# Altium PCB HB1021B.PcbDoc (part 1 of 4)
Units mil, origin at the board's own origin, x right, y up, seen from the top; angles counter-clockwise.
Board outline 4729.44 x 3075.9 mil, 2 copper layers (Top Layer, Bottom Layer); 113 components, 113 nets, 422 pads, 478 vias.
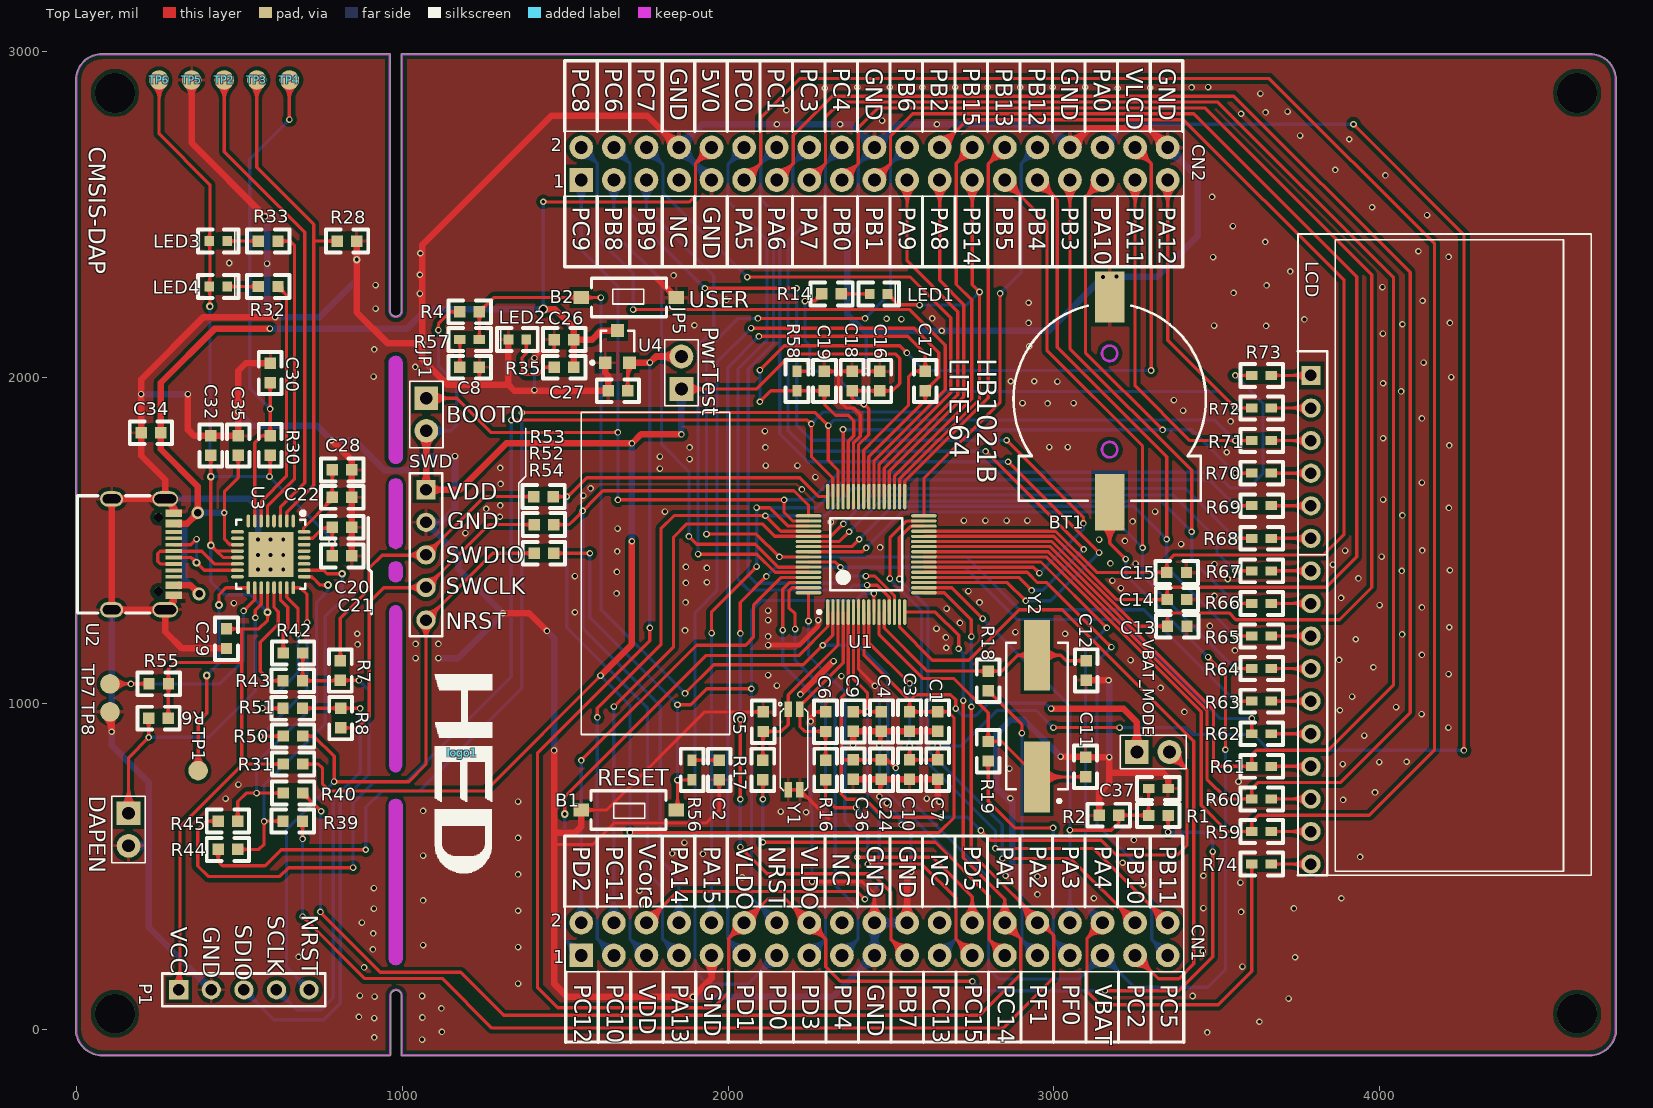
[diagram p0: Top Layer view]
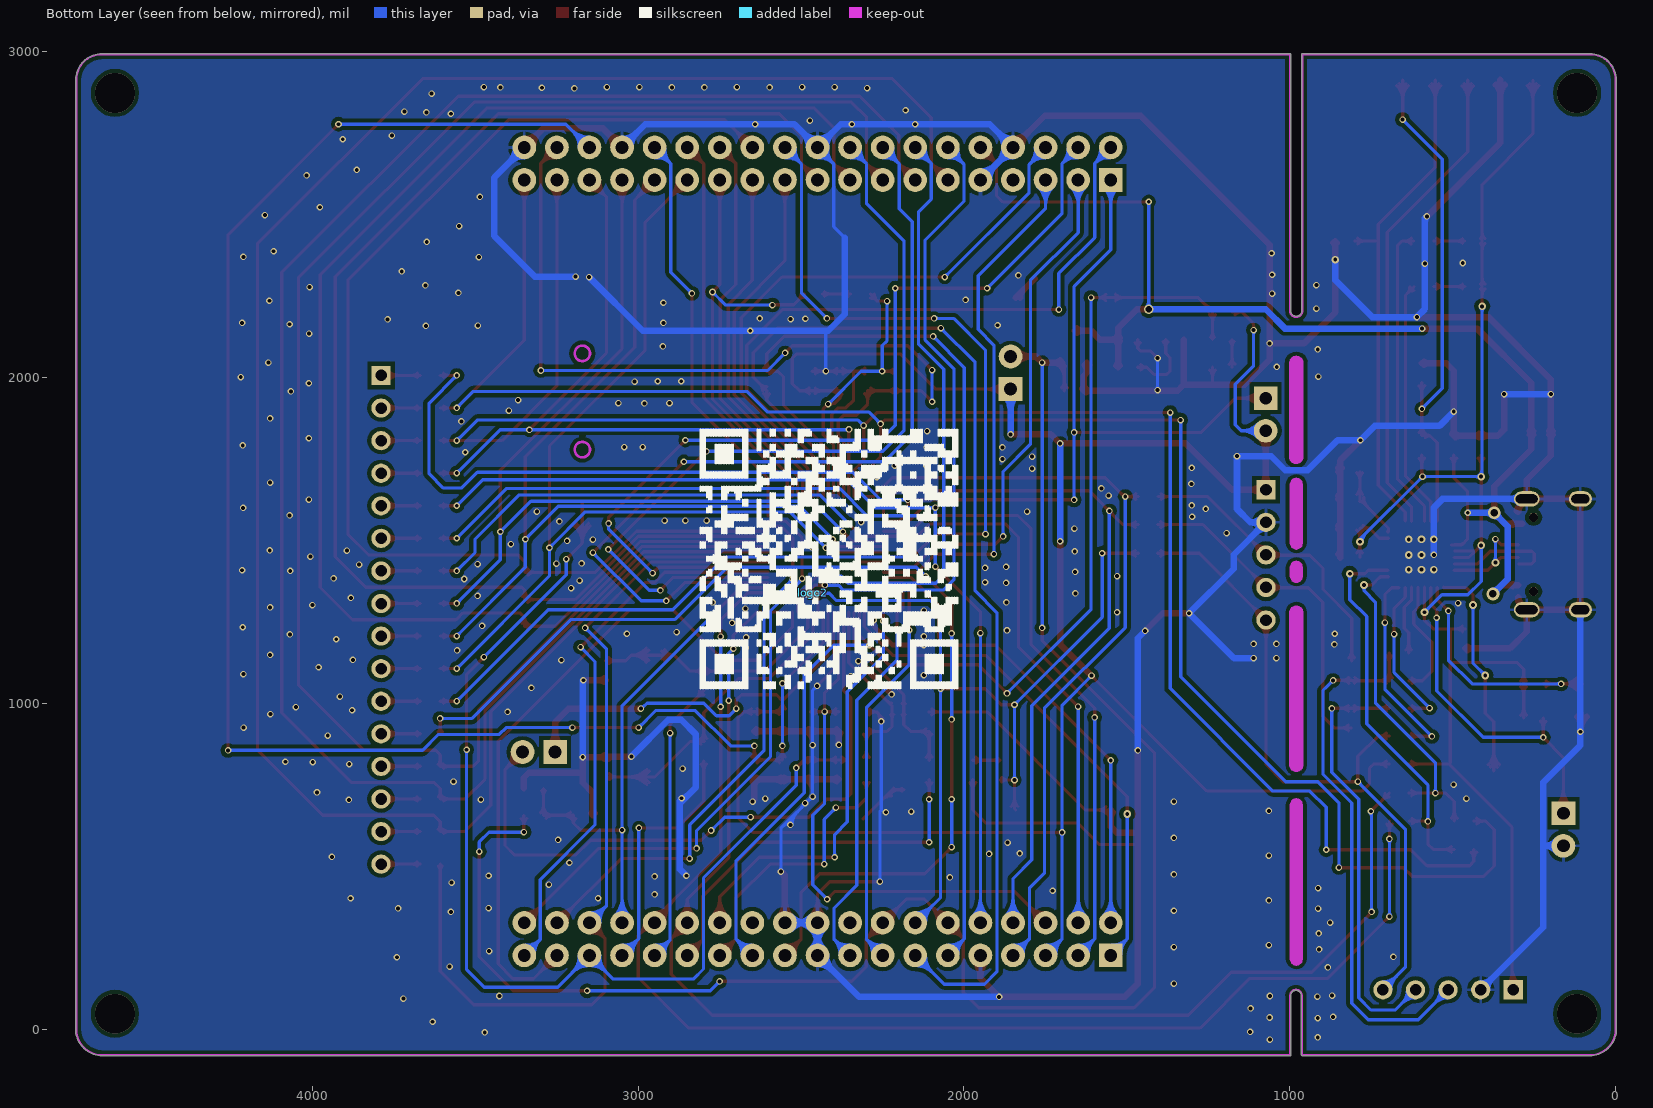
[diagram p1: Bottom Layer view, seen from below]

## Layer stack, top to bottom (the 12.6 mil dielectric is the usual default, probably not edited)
Top Layer: signal copper 1.4
Dielectric: dielectric 12.6, FR-4, Dk 4.8
Bottom Layer: signal copper 1.4

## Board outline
-2.52,0.05 ccw(c78.74,0.05) 78.74,-81.21 ccw(c78.74,-78.69) 78.81,-81.21 962,-81.21 ccw(c962,-78.69) 964.52,-78.69 964.52,103 cw(c981,103) 997.44,104.27 ccw(c999.61,103) 997.09,103 997.09,-78.69 ccw(c999.61,-78.69) 999.61,-81.21 4645.67,-81.21 ccw(c4645.67,0.05) 4726.92,0.05 ccw(c4724.41,0.05) 4726.92,0.07 4726.92,2913.43 cw(c4724.41,2913.43) 4726.92,2913.41 4726.92,2913.43 ccw(c4645.67,2913.43) 4645.73,2994.69 ccw(c4645.67,2992.17) 4645.67,2994.69 1000,2994.69 ccw(c1000,2992.17) 997.48,2992.17 997.48,2204.83 cw(c1000,2204.83) 997.48,2204.88 997.48,2204.83 cw(c980.31,2204.83) 995.99,2197.82 cw(c980.45,2206.4) 963.65,2200.68 cw(c980.31,2204.83) 963.14,2204.77 cw(c980.31,2204.83) 963.14,2204.83 963.14,2992.17 ccw(c960.63,2992.17) 960.12,2994.64 ccw(c959.61,2992.17) 959.61,2994.69 78.8,2994.69 ccw(c78.8,2992.17) 78.74,2994.69 cw(c78.8,2913.43) 78.8,2994.69 78.74,2994.69 ccw(c78.8,2913.43) -2.45,2913.99 ccw(c0,2913.43) -2.51,2913.43
cut-out: 959.99,217 959.99,687 cw(c980,687) 1000.02,687 1000.02,217 cw(c980,217)
cut-out: 959.99,1392 959.99,1416 cw(c980,1416) 1000.02,1416 1000.02,1392 cw(c980,1392)
cut-out: 959.99,1494 959.99,1671 cw(c980,1671) 1000.02,1671 1000.02,1494 cw(c980,1494)
cut-out: 959.99,810 ccw(c980,810) 1000.02,810 1000.02,1280 ccw(c980,1280) 959.99,1280
cut-out: 998.94,1756.79 998.94,2045.37 ccw(c979.25,2045.37) 959.57,2045.37 959.57,1756.79 ccw(c979.25,1756.79)

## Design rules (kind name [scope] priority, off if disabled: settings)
Clearance [(IsPad and InComponent('U1'))] p1: gap=5
Clearance Clearance_CN [(IsPad and InComponent('CN1','CN4','U2'))] p2: gap=6
Clearance Clearance_Pad [All] p3: gap=5
Clearance Clearance_poly [(InPolygon)] p4: gap=12
ComponentClearance [All] p1: gap=0 collisioncheckmode=3 verticalgap=0 showdistances=FALSE
HoleSize [All] p1: absolutevalues=TRUE maxlimit=130 minlimit=1 maxpercent=80.000 minpercent=20.000
MinimumSolderMaskSliver [All] p1: minsoldermaskwidth=0
PolygonConnect PolygonConnect_Pads [IsPad] p1: connectstyle=Relief reliefconductorwidth=10 reliefentries=4 polygonreliefangle="90 Angle"
PolygonConnect [All] p2: connectstyle=Direct reliefconductorwidth=10 reliefentries=4 polygonreliefangle="90 Angle"
RoutingVias [All] p1: holewidth=12 width=20 viastyle="Through Hole" minholewidth=10 minwidth=18 maxholewidth=300 maxwidth=500
SilkToSilkClearance [All] p1: silktosilkclearance=0
SilkscreenOverComponentPads [IsPad] p1: minsilkscreentomaskgap=0
SolderMaskExpansion [All] p1: expansion=4
TestPointUsage [All] p1: valid=0 allowmultiple=FALSE
Testpoint [All] p1: side=3 testpointundercomponent=TRUE minsize=40 maxsize=100 preferedsize=60 minholesize=0 maxholesize=40 preferedholesize=32 testpointgrid=1 style=297 order=0123456789
Width [All] p1: maxlimit=20 minlimit=8 preferedwidth=10
19 further rules are at their usual default settings.

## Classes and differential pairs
component class LINK: C20 C21 C22 C28 C29 C30 C32 C34 C35 D4 DAPEN JP6 JP9 LED3 LED4 P0 P1 R6 R7 R8 R28 R30 R31 R32 R33 R38 R39 R40 R42 R43 R44 R45 R47 R48 R49 R50 R51 R55 TP1 TP2 TP3 TP4 TP5 TP6 TP7 TP8 U2 U3
component class mcu: B1 B2 BT1 C1 C2 C3 C4 C5 C6 C7 C8 C9 C10 C11 C12 C13 C14 C15 C16 C17 C18 C19 C24 C26 C27 C36 C37 CN1 CN2 D1 JP1 JP5 LCD LED1 LED2 logo1 logo2 R1 R2 R4 R14 R16 R17 R18 R19 R35 R52 R53 R54 R56 R57 R58 R59 R60 R61 R62 R63 R64 R65 R66 R67 R68 R69 R70 R71 R72 R73 R74 SWD U1 U4 VBAT_MODE Y1 Y2

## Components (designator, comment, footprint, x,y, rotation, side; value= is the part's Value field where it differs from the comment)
B1 "TS-1101-C-W" 按键_TS-1101-C-W 1549.61,673 r0 top
B2 "TS-1101-C-W" 按键_TS-1101-C-W 1840.95,2246 r180 top
BT1 "CR1220电池座" CR1220 3171.61,1617.79 r90 top locked
C1 "4.7u" 0603#1 2643.6,914.79 r90 top
C2 "0.1u" 0603#1 1973,826 r270 top
C3 "0.1u" 0603#1 2557.27,914.79 r90 top
C4 "0.1u" 0603#1 2470.93,974.79 r270 top
C5 "10p" 0603#1 2108,974 r270 top
C6 "10p" 0603#1 2299.61,974 r270 top
C7 "1u" 0603#1 2643.6,766.79 r90 top
C8 "0.1u" 0603#1 1237,2032 r180 top
C9 "1u" 0603#1 2384.6,974.79 r270 top
C10 "0.1u" 0603#1 2557.27,766.79 r90 top
C11 "DNP" 0603#1 3097.61,775.31 r90 top
C12 "DNP" 0603#1 3099.61,1131.31 r270 top
C13 "0.1u" 0603#1 3349,1237 r0 top
C14 "0.1u" 0603#1 3348,1319 r0 top
C15 "0.1u" 0603#1 3347.29,1402.11 r0 top
C16 "4.7u" 0603#1 2466,1959.79 r90 top
C17 "0.1u/DNP" 0603#1 2605.61,1959.79 r90 top
C18 "0.1u" 0603#1 2381,1959.79 r90 top
C19 "0.1u" 0603#1 2296,2019.79 r270 top
C20 "1u" 0603#1 845.61,1540.79 r180 top
C21 "10n" 0603#1 845.61,1452.79 r180 top
C22 "4.7u" 0603#1 845.61,1632.79 r180 top
C24 "1u" 0603#1 2470.93,766.79 r90 top
C26 "10u" 0603#1 1467,2117 r0 top
C27 "10u" 0603#1 1632,1960 r0 top
C28 "0.1u" 0603#1 845.61,1716.79 r180 top
C29 "0.1u" 0603#1 460.61,1168.79 r90 top
C30 "0.1u" 0603#1 594.61,1984.31 r90 top
C32 "1u" 0603#1 412.61,1761.79 r90 top
C34 "0.1u" 0603#1 198.61,1830.79 r0 top
C35 "1u" 0603#1 496.61,1761.79 r90 top
C36 "0.1u" 0603#1 2384.6,766.79 r90 top
C37 "0.1u" 0603#2 3291,739 r0 top
CN1 "Header 19x2" HEADER_1X19_2.54 1549.61,226.79 r0 top locked
CN2 "Header 19x2" HEADER_1X19_2.54 1549.61,2606.79 r0 top
DAPEN "Header 1x2" HEADER_1X2_2.54 160,613 r270 top (schematic designator DAP_EN)
JP1 "Header 1x2" HEADER_1X2_2.54 1074,1887 r270 top
JP5 "Header 1x2" HEADER_1X2_2.54 1857,2015 r90 top
LCD "YR1213C_4COM*8SEG" LCD_YR_8COM*8SEG 3749.46,2637.84 r270 top locked
LED1 "LED_G" "0603 - p" 2435,2257 r0 top
LED2 "LED_R" 0603-P 1381,2117 r180 top
LED3 "LED_G" 0603-P 407.61,2419.31 r0 top
LED4 "LED_R" 0603-P 407.61,2279.79 r0 top
logo1 "logo" LOGO 1184,848 r270 top
logo2 "SIGN" SIGN 2465,1340 r90 bottom
P1 "Header 1x5" HDR1X5_2.54 314,121 r0 top
R1 "47K" 0603#1 3291,656 r0 top
R2 "47K" 0603#1 3139,657 r0 top
R4 "4.7k" 0603#1 1237,2202 r180 top
R6 "4.7K" 0603#1 222,955 r0 top
R7 "0R" 0603#1 810,1071 r90 top
R8 "0R" 0603#1 811,985 r270 top
R14 "510R" 0603#1 2348,2257 r180 top
R16 "DNP" 0603#1 2299.61,766 r90 top
R17 "DNP" 0603#1 2107,766 r90 top
R18 "0R" 0603#1 2798.61,1099.31 r270 top
R19 "0R" 0603#1 2798.61,883.31 r270 top
R28 "DNP" 0603#1 860.61,2419.31 r180 top
R30 "DNP" 0603#1 594.61,1762.31 r90 top
R31 "DNP" 0603#1 635,814 r0 top
R32 "1K" 0603#1 618.61,2279.79 r180 top
R33 "1K" 0603#1 618.61,2419.31 r180 top
R35 "1K" 0603#1 1467,2032 r0 top
R39 "0R" 0603#1 634,639 r0 top
R40 "0R" 0603#1 635,725 r0 top
R42 "150R" 0603#1 635,1155 r0 top
R43 "150R" 0603#1 634,1070 r0 top
R44 "DNP" 0603#1 495,552 r180 top
R45 "DNP" 0603#1 495,639 r180 top
R50 "150R" 0603#1 635,900 r0 top
R51 "150R" 0603#1 634,985 r0 top
R52 "51R" 0603#1 1405,1549 r0 top
R53 "51R" 0603#1 1404,1635 r0 top
R54 "51R" 0603#1 1405,1461 r0 top
R55 "4.7K" 0603#1 282.61,1060.31 r180 top
R56 "10R" 0603#2 1890,766 r90 top
R57 "10R" 0603#2 1237,2117 r180 top
R58 "0R/DNP" 0603#2 2212,1959.79 r90 top
R59 "0R" 0603#2 3608,607 r0 top
R60 "0R" 0603#2 3608,707 r0 top
R61 "0R" 0603#2 3608,807 r0 top
R62 "0R" 0603#2 3608,907 r0 top
R63 "0R" 0603#2 3608,1007 r0 top
R64 "0R" 0603#2 3608,1107 r0 top
R65 "0R" 0603#2 3608,1207 r0 top
R66 "0R" 0603#2 3608,1307 r0 top
R67 "0R" 0603#2 3608,1407 r0 top
R68 "0R" 0603#2 3608,1507 r0 top
R69 "0R" 0603#2 3608,1607 r0 top
R70 "0R" 0603#2 3608,1707 r0 top
R71 "0R" 0603#2 3608,1807 r0 top
R72 "0R" 0603#2 3608,1907 r0 top
R73 "0R" 0603#2 3608,2007 r0 top
R74 "0R" 0603#2 3608,507 r0 top
SWD "Header 1x5" HDR1X5_2.54 1073,1656 r270 top
TP1 "TEST_POINT" TEST_POINT 335.61,798.79 r180 top
TP2 "TEST_POINT" TEST_POINT 415.61,2918.79 r180 top locked
TP3 "TEST_POINT" TEST_POINT 515.61,2918.79 r180 top locked
TP4 "TEST_POINT" TEST_POINT 615.61,2918.79 r180 top locked
TP5 "TEST_POINT" TEST_POINT 315.61,2918.79 r180 top locked
TP6 "TEST_POINT" TEST_POINT 258.61,2951.79 r90 top locked
TP7 "TEST_POINT" TEST_POINT 108.04,1098 r90 top
TP8 "TEST_POINT" TEST_POINT 108.04,1012 r90 top
U1 "MCU" LQFP_64N_7X7 2424.27,1457.79 r90 top locked
U2 "TYPE-C-16P" HED-KH-TYPE-C-16P 272.61,1627.79 r270 top
U3 "CIU98_H" HED-QFN-32_5x5x05P 596.61,1457.79 r180 top
U4 "ME6210A33M3G" SOT-23-3 1658,2091 r0 top
VBAT_MODE "Header 1x2" HEADER_1X2_2.54 3305,851 r0 top
Y1 "32.768KHz" XTAL-MC146 2185.27,982.79 r270 top
Y2 "DNP" XTAL_HC49/SMD 2948.61,961.31 r90 top

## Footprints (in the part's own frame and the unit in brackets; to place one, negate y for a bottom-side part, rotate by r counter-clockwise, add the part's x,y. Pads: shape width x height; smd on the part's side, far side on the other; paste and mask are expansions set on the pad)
0603#1 [mil]
  rect 35x35 smd: 1(0,0) 2(60,0)
  silkscreen extent -35,-35 95,35
0603#2 [mil]
  rect 35x27.56 smd: 1(0,0) 2(60,0)
  silkscreen extent -35,-35 95,35
"0603 - p" [mil]
  rect 30x30 smd: 1(0,0) 2(55,0)
  silkscreen extent -35,-35 90,35, body extent 1,-15 60,15, height 10
0603-P [mil]
  rect 30x30 smd: 1(0,0) 2(55,0)
  silkscreen extent -35,-35 90,35, body extent 1,-15 60,15, height 10
CR1220 [mm]
  rect 4.4x2.3 smd: 1(0,0)
  rect 4x2.3 smd: 2(16,0)
  Keep-Out Layer circle w0.203: c11.6,0 r0.6
  Keep-Out Layer circle w0.203: c4.1,0 r0.6
  silkscreen extent 0.1,-7.5 15.31,7.5
HDR1X5_2.54 [mm]
  rect 1.5x1.5 hole 0.9: 1(0,0)
  round 1.5 hole 0.9: 2(2.54,0) 3(5.08,0) 4(7.62,0) 5(10.16,0)
  silkscreen extent -1.27,-1.27 11.43,1.27
HEADER_1X2_2.54 [mm]
  rect 1.85x1.85 / inner round 1.85 / far side rect 1.85x1.85 hole 1: 1(-1.27,0)
  round 1.85 hole 1: 2(1.27,0)
  silkscreen extent -2.58,-1.3 2.58,1.3, body extent -2.67,-1.3 2.58,1.3, height 8.38
HEADER_1X19_2.54 [mm]
  rect 1.85x1.85 / inner round 1.85 / far side rect 1.85x1.85 hole 1: 1(0,0)
  round 1.85 hole 1: 2(0,2.54) 3(2.54,0) 4(2.54,2.54) 5(5.08,0) 6(5.08,2.54) 7(7.62,0) 8(7.62,2.54) 9(10.16,0) 10(10.16,2.54) 11(12.7,0) 12(12.7,2.54) 13(15.24,0) 14(15.24,2.54) 15(17.78,0) 16(17.78,2.54) 17(20.32,0) 18(20.32,2.54) 19(22.86,0) 20(22.86,2.54) 21(25.4,0) 22(25.4,2.54) 23(27.94,0) 24(27.94,2.54) 25(30.48,0) 26(30.48,2.54) 27(33.02,0) 28(33.02,2.54) 29(35.56,0) 30(35.56,2.54) 31(38.1,0) 32(38.1,2.54) 33(40.64,0) 34(40.64,2.54) 35(43.18,0) 36(43.18,2.54) 37(45.72,0) 38(45.72,2.54)
  silkscreen extent -1.27,-1.27 46.99,3.81, body extent -1.27,-1.27 46.99,3.81, height 8.38
HED-KH-TYPE-C-16P [mm]
  oval 1.2x2 hole 0.7 slot 1.7 at 90 deg: 1(0,0) 2(8.64,0)
  oval 1.2x1.8 hole 0.7 slot 1.4 at 90 deg: 3(0,-4.18) 4(8.64,-4.18)
  rect 0.3x1.3 smd: A1(0.97,0.65) A4(1.77,0.65) A5(3.07,0.65) A6(4.07,0.65) A7(4.57,0.65) A8(5.57,0.65) A9(6.87,0.65) A12(7.67,0.65) B1(7.37,0.65) B4(6.57,0.65) B5(6.07,0.65) B6(5.07,0.65) B7(3.57,0.65) B8(2.57,0.65) B9(2.07,0.65) B12(1.27,0.65)
  round 0.7 hole 0.7 unplated: ""(1.43,-0.53) ""(7.21,-0.53)
  silkscreen extent -0.25,-6.84 8.89,-1.19
HED-QFN-32_5x5x05P [mm]
  oval 0.28x1 smd: 1(-1.75,-2.6) 2(-1.25,-2.6) 3(-0.75,-2.6) 4(-0.25,-2.6) 5(0.25,-2.6) 6(0.75,-2.6) 7(1.25,-2.6) 8(1.75,-2.6) 17(1.75,2.6) 18(1.25,2.6) 19(0.75,2.6) 20(0.25,2.6) 21(-0.25,2.6) 22(-0.75,2.6) 23(-1.25,2.6) 24(-1.75,2.6)
  oval 1x0.28 smd: 9(2.6,-1.75) 10(2.6,-1.25) 11(2.6,-0.75) 12(2.6,-0.25) 13(2.6,0.25) 14(2.6,0.75) 15(2.6,1.25) 16(2.6,1.75) 25(-2.6,1.75) 26(-2.6,1.25) 27(-2.6,0.75) 28(-2.6,0.25) 29(-2.6,-0.25) 30(-2.6,-0.75) 31(-2.6,-1.25) 32(-2.6,-1.75)
  rect 3.5x3.5 smd: 33(0,0)
  silkscreen extent -2.7,-3.35 2.7,2.7
LCD_YR_8COM*8SEG [mm] "5V 8COM*8SEG"
  rect 1.5x1.5 hole 0.9: 1(16.03,1.016)
  round 1.5 hole 0.9: 2(18.57,1.016) 3(21.11,1.016) 4(23.65,1.016) 5(26.19,1.016) 6(28.73,1.016) 7(31.27,1.016) 8(33.81,1.016) 9(36.35,1.016) 10(38.89,1.016) 11(41.43,1.016) 12(43.97,1.016) 13(46.51,1.016) 14(49.05,1.016) 15(51.59,1.016) 16(54.13,1.016)
  silkscreen extent 5,0 55,22.86
LOGO [mil]
  silkscreen extent -241,-83 369,93
LQFP_64N_7X7 [mm] "TSQFP, 64-Leads, Body 9.2x9.2mm (max), Pitch 0.40mm, IPC Medium Density"
  oval 2x0.25 smd: 1(-4.5,3) 2(-4.5,2.6) 3(-4.5,2.2) 4(-4.5,1.8) 5(-4.5,1.4) 6(-4.5,1) 7(-4.5,0.6) 8(-4.5,0.2) 9(-4.5,-0.2) 10(-4.5,-0.6) 11(-4.5,-1) 12(-4.5,-1.4) 13(-4.5,-1.8) 14(-4.5,-2.2) 15(-4.5,-2.6) 16(-4.5,-3) 33(4.5,-3) 34(4.5,-2.6) 35(4.5,-2.2) 36(4.5,-1.8) 37(4.5,-1.4) 38(4.5,-1) 39(4.5,-0.6) 40(4.5,-0.2) 41(4.5,0.2) 42(4.5,0.6) 43(4.5,1) 44(4.5,1.4) 45(4.5,1.8) 46(4.5,2.2) 47(4.5,2.6) 48(4.5,3)
  oval 0.25x2 smd: 17(-3,-4.5) 18(-2.6,-4.5) 19(-2.2,-4.5) 20(-1.8,-4.5) 21(-1.4,-4.5) 22(-1,-4.5) 23(-0.6,-4.5) 24(-0.2,-4.5) 25(0.2,-4.5) 26(0.6,-4.5) 27(1,-4.5) 28(1.4,-4.5) 29(1.8,-4.5) 30(2.2,-4.5) 31(2.6,-4.5) 32(3,-4.5) 49(3,4.5) 50(2.6,4.5) 51(2.2,4.5) 52(1.8,4.5) 53(1.4,4.5) 54(1,4.5) 55(0.6,4.5) 56(0.2,4.5) 57(-0.2,4.5) 58(-0.6,4.5) 59(-1,4.5) 60(-1.4,4.5) 61(-1.8,4.5) 62(-2.2,4.5) 63(-2.6,4.5) 64(-3,4.5)
  silkscreen extent -4.62,-2.8 2.8,3.8, body extent -3.5,-3.5 3.5,3.5, height 1.4
SIGN [mil]
  silkscreen extent -294,-446 501,344
SOT-23-3 [mm]
  rect 1x1 smd: 1(-0.889,-1.143) 2(1.011,-1.143) 3(0.061,1.357)
  silkscreen extent -2.01,-1.27 1.36,1.36, body extent -1.39,-1.29 1.51,1.51, height 1.2
TEST_POINT [mil]
  round 60 smd: 1(-38,5)
XTAL-MC146 [mm]
  rect 1.2x0.6 smd mask+0.05: 1(0,0) 2(6.3,0) 3(6.3,0.9) 4(0,0.9)
  silkscreen extent -0.51,-0.76 6.35,1.52
XTAL_HC49/SMD [mm]
  rect 5.5x2 smd: 1(-4.75,0) 2(4.75,0)
  silkscreen extent -6.75,-2.4 5.7,2.4, body extent -6.7,-2.46 6.7,2.44, height 4
按键_TS-1101-C-W [mm] "星坤品牌"
  rect 1.2x1 smd mask+0.05: 1(0,0) 2(7.4,0)
  silkscreen extent 0.76,-1.5 6.6,1.5

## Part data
B1 B2: library part SW-PB, "Switch"
BT1: library part Battery, "Multicell Battery"
C1 C11 C12 C13 C14 C15 C16 C17 C19 C36 C37: library part MCD-00009, "Capacitor, MLCC, 4.7uF, 16V, X5R, 10%, 0603, T=0.8mm"
C2 C3 C4 C7 C9 C10 C18 C20 C21 C28 C29 C30 C32 C35: library part MCD-00211, "Capacitor, MLCC, 100nF, 16V, X7R, 10%, 0603, T=0,8mm"
C5 C6: library part Capacitor, "Capacitor,5.6pF,0.1pF,16V,NPO,0603"
C8: library part MCD-00211, "贴片电容"
C22 C34: library part "0603 100nF 10% 50V", "贴片电容"
C24 C26 C27: library part MCD-00014, "Capacitor, MLCC, 10uF, 25V, X5R, 10%, 0805, T=0,85mm"
CN1 CN2: "Header, 19x2, 2,54mm, VR, TH, Height 5.84mm/10.16mm"
DAPEN VBAT_MODE: library part MCD-00683, "Header, 2x1, 2,54mm, VR, TH, Height 5.84mm/2.54mm - Shunt Fitted by default"
JP1 JP5: library part "Jumper_Header 2x1 Fitted", "Header, 2x1, 2,54mm, VR, TH, Height 5.84mm/2.54mm - Shunt Fitted by default"
LCD: library part LCD8COM*8SEG, "Common Anode Seven-Segment Display, Right Hand Decimal"
LED1 LED2 LED3 LED4: library part LED1, "Typical RED GaAs LED"
P1 SWD: library part SWD
R1 R2 R4 R6 R7 R8 R14 R16 R17 R18 R19 R30 R31 R32 R33 R35 R39 R40 R44 R45 R56 R57 R58 R59 R60 R61 R62 R63 R64 R65 R66 R67 R68 R69 R70 R71 R72 R73 R74: library part Res2, "贴片电阻"
R28 R42 R43 R50 R51 R52 R53 R54 R55: library part Res, "贴片电阻"
U1: library part CIU32L071Rx-LQFP64, "CIU32L071Rx"
U2: library part KH-TYPE-C-16P, "TYPE-C USB接口"
U3: library part CIU98-H
U4: library part ME6210, "贴片LDO3.3V"
Y1: library part MC146
Y2: library part XTAL_32K_NX3215SA, "Crystal 32.768kHz, 6pF, -+20PPM, R=50K, SMD"

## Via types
v1: diameter 20, hole 12, Top Layer to Bottom Layer, tented both sides, 451 vias
v2: diameter 23.62, hole 11.81, Top Layer to Bottom Layer, tented both sides, 20 vias
v3: diameter 122.05, hole 122.05, Top Layer to Bottom Layer, tented both sides, 4 vias
v4: diameter 39.37, hole 23.62, Top Layer to Bottom Layer, tented both sides, 2 vias
v5: diameter 30, hole 20, Top Layer to Bottom Layer, tented both sides, 1 vias

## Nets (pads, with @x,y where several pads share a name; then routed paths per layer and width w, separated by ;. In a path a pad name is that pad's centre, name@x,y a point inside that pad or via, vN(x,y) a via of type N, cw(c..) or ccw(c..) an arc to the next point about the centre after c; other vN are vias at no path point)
CMS_STATE: TP1.1 U3.17 | length 922.9
  Top Layer w10: TP1.1@355.93,811.47 ccw(c313.25,854.14) 373.61,854.14 ccw(c433.96,854.14) TP1.1@391.28,811.47 ; TP1.1@363,804.39 ccw(c337.39,830) 373.61,830 ccw(c409.82,830) TP1.1@384.21,804.39 ; TP1.1@373.61,793.79 373.61,943.79 400,970.18 v2(400,1086) ; v2@395.18,1081.18 cw(c383.56,1069.56) 400,1069.56 cw(c416.44,1069.56) v2@404.82,1081.18 ; v2@432.79,1307.12 ccw(c421.16,1318.75) 437.61,1318.75 ccw(c454.05,1318.75) v2@442.42,1307.12 ; v2(437.61,1302.31) 437.61,1334.31 458.72,1355.43 U3.17@527.71,1355.43 U3.17@527.71,1357.39
  Bottom Layer w10: v2(400,1086) 437.61,1123.61 v2(437.61,1302.31) ; v2@400,1092.81 ccw(c400,1109.25) 411.63,1097.63 ccw(c423.25,1086) v2@406.81,1086 ; v2@432.79,1297.49 cw(c421.16,1285.86) 437.61,1285.86 cw(c454.05,1285.86) v2@442.42,1297.49
GND: B1.1 B2.1 BT1.2 C1.1 C2.2 C3.1 C4.2 C5.1 C6.1 C7.1 C8.1 C9.2 C10.1 C11.2 C12.2 C13.2 C14.2 C15.2 C16.2 C18.2 C19.1 C20.1 C21.1 C22.1 C24.1 C26.1 C27.1 C28.1 C29.1 C30.2 C32.2 C34.1 C35.2 C36.1 C37.2 CN1.9 CN1.19 CN1.20 CN1.22 CN2.8 CN2.9 CN2.20 CN2.32 CN2.38 DAPEN.2 LED2.2 P1.2 R2.1 R28.1 SWD.2 TP5.1 TP8.1 U1.7 U1.43 U2.1 U2.2 U2.3 U2.4 U2.A1 U2.A12 U2.B1 U2.B12 U3.33 U4.1 Y1.2 Y1.3 | length 29898
  Top Layer w10: C8.1@1228.16,2023.16 cw(c1206.82,2001.82) 1237,2001.82 cw(c1267.18,2001.82) C8.1@1245.84,2023.16 ; 1237,1979 C8.1@1237,2032 ; v1(1406,2060) 1428,2082 1459,2082 1467,2090 ; v1@1406,2065 ccw(c1406,2077.07) 1414.54,2068.54 ccw(c1423.07,2060) v1@1411,2060 ; C26.1@1458.91,2107.47 cw(c1444.09,2090) 1467,2090 ; 1466,567 1585,567 1651,633 1933,633 1973,673 C2.2@1973,766 ; C26.1@1467,2117 1467,2090 ; C26.1@1475.09,2107.47 ccw(c1489.91,2090) 1467,2090 ; B1.1@1549.61,673 1628,673 1929,974 C5.1@2108,974 ; B1.1@1563.93,662.62 cw(c1589,637.55) 1589,673 cw(c1589,708.45) B1.1@1563.93,683.38 ; C2.2@1964.16,757.16 cw(c1942.82,735.82) 1973,735.82 cw(c2003.18,735.82) C2.2@1981.84,757.16 ; C5.1@2099.16,965.16 ccw(c2077.82,943.82) 2077.82,974 ccw(c2077.82,1004.18) C5.1@2099.16,982.84 ; Y1.2@2185.27,734.76 Y1.3@2220.7,734.76 2309.46,646 ; Y1.2@2190.08,729.94 cw(c2201.71,718.31) 2201.71,734.76 cw(c2201.71,751.2) Y1.2@2190.08,739.57 ; Y1.3@2215.88,729.94 ccw(c2204.26,718.31) 2204.26,734.76 ccw(c2204.26,751.2) Y1.3@2215.88,739.57 ; Y1.3@2220.7,716.13 cw(c2220.7,671.18) 2252.49,702.97 ; Y1.3@2220.7,726.13 cw(c2220.7,705.32) 2235.42,720.04 ; v1@2249.07,944.19 cw(c2267.27,947.18) 2254.22,960.22 ; v1@2250.46,948.54 ccw(c2241.93,957.07) 2254,957.07 ccw(c2266.07,957.07) v1@2257.54,948.54 ; v1(2254,945) 2254,960 2268,974 ; v1(2258,453) 2412,453 2449.61,415.39 CN1.20@2449.61,326.79 ; v1@2258.93,945.81 cw(c2290.93,951.07) 2268,974 ; v1@2261.54,449.46 cw(c2270.07,440.93) 2270.07,453 cw(c2270.07,465.07) v1@2261.54,456.54 ; C6.1@2290.77,965.16 ccw(c2269.43,943.82) 2269.43,974 ccw(c2269.43,1004.18) C6.1@2290.77,982.84 ; C19.1@2296,2019.79 C18.2@2381,2019.79 C16.2@2466,2019.79 ; C6.1@2299.61,974 2268,974 ; C19.1@2304.84,2010.95 cw(c2326.18,1989.61) 2326.18,2019.79 cw(c2326.18,2049.97) C19.1@2304.84,2028.63 ; 2339,2018.79 2339,1931 2363,1907 2386,1907 2406,1887 2406,1820.21 2384.9,1799.11 U1.43@2384.9,1634.95 ; C18.2@2372.16,2010.95 ccw(c2350.82,1989.61) 2350.82,2019.79 ccw(c2350.82,2049.97) C18.2@2372.16,2028.63 ; C18.2@2389.84,2010.95 cw(c2411.18,1989.61) 2411.18,2019.79 cw(c2411.18,2049.97) C18.2@2389.84,2028.63 ; U1.7@2400.65,1280.62 2400.65,1104.35 v1(2451,1054) ; 2411.42,2019.79 ccw(c2411.42,2032.58) v1@2420.46,2023.54 ; 2412.44,2019.79 cw(c2412.44,2008.44) v1@2420.46,2016.46 ; CN1.20@2427.39,349 ccw(c2373.76,402.64) 2449.61,402.64 ccw(c2525.45,402.64) CN1.20@2471.82,349 ; v1@2427.54,2016.46 cw(c2435.56,2008.44) 2435.56,2019.79 ; v1@2427.54,2023.54 ccw(c2436.58,2032.58) 2436.58,2019.79 ; CN1.20@2434.46,341.93 ccw(c2397.9,378.49) 2449.61,378.49 ccw(c2501.31,378.49) CN1.20@2464.75,341.93 ; v1@2446,1054 ccw(c2433.93,1054) 2442.46,1062.54 ccw(c2451,1071.07) v1@2451,1059 ; C16.2@2457.16,2010.95 ccw(c2435.82,1989.61) 2435.82,2019.79 ccw(c2435.82,2049.97) C16.2@2457.16,2028.63 ; v1@2461.46,717.36 ccw(c2452.93,725.89) 2465,725.89 ccw(c2477.07,725.89) v1@2468.54,717.36 ; v1@2461.46,875.54 ccw(c2452.93,884.07) 2465,884.07 ccw(c2477.07,884.07) v1@2468.54,875.54 ; v1(2465,713.82) C24.1@2465,760.85 ; v1@2465,722.28 cw(c2515.44,722.28) C24.1@2479.77,757.95 ; 2465,746.42 cw(c2491.3,746.42) C24.1@2472.7,765.02 ; v1@2465,871.59 cw(c2512.33,871.59) C4.2@2479.58,905.76 ; v1(2465,872) C4.2@2465,908.85 ; 2465,895.02 cw(c2489.87,895.02) C4.2@2472.66,912.98
  Top Layer w15: v1(2123,1179) 2219,1179 2277,1237 v1(2277,1256)
  Top Layer w20: TP8.1@88.9,959.86 cw(c42.69,913.64) v1@108.04,913.64 ; U2.4@98.41,1297.26 ccw(c75.15,1320.52) 108.04,1320.52 ccw(c140.93,1320.52) U2.4@117.67,1297.26 ; U2.3@98.41,1618.16 cw(c75.15,1594.9) 108.04,1594.9 cw(c140.93,1594.9) U2.3@117.67,1618.16 ; v1(108.04,913) TP8.1@108.04,969 ; 108.04,937.79 cw(c139.25,937.79) TP8.1@117.18,959.86 ; U2.4@129.48,1278 cw(c152.74,1254.75) 152.74,1287.63 cw(c152.74,1320.52) U2.4@129.48,1297.26 ; U2.3@129.48,1618.16 cw(c152.74,1594.9) 152.74,1627.79 cw(c152.74,1660.67) U2.3@129.48,1637.42 ; C34.1@193.3,1825.48 cw(c180.5,1812.68) 198.61,1812.68 cw(c216.71,1812.68) C34.1@203.91,1825.48 ; C34.1@193.3,1836.09 ccw(c180.5,1848.89) 198.61,1848.89 ccw(c216.71,1848.89) C34.1@203.91,1836.09 ; U2.2@247.23,1278 ccw(c223.97,1254.75) 223.97,1287.63 ccw(c223.97,1320.52) U2.2@247.23,1297.26 ; U2.1@247.23,1618.16 ccw(c223.97,1594.9) 223.97,1627.79 ccw(c223.97,1660.67) U2.1@247.23,1637.42 ; U2.2@262.97,1278 cw(c239.72,1254.75) 272.61,1254.75 cw(c305.49,1254.75) U2.2@282.24,1278 ; U2.1@262.97,1637.42 ccw(c239.72,1660.67) 272.61,1660.67 ccw(c305.49,1660.67) U2.1@282.24,1637.42 ; U2.1@281.86,1615.81 cw(c266.96,1588.35) U2.A1@298.2,1588.35 ; U2.2@282.2,1299.79 ccw(c269.03,1325.82) U2.A12@298.2,1325.82 298.2,1313.23 U2.2@272.61,1287.63 ; 296.83,1603.56 cw(c282.87,1589.6) U2.A1@302.61,1589.6 ; U2.A1@298.2,1589.6 298.2,1602.19 U2.1@272.61,1627.79 ; TP5.1@339.46,2899.65 cw(c305.32,2865.5) 353.61,2865.5 cw(c401.89,2865.5) TP5.1@367.75,2899.65 ; v1(342.39,1949.39) 342.39,1840.61 361.21,1821.79 C32.2@412.61,1821.79 C35.2@496.61,1821.79 v1(496.61,1896) 496.61,2021.31 519.61,2044.31 C30.2@594.61,2044.31 ; TP5.1@353.61,2913.79 353.61,2720.39 v1(579,2495) ; C32.2@407.3,1816.48 ccw(c394.5,1803.68) 394.5,1821.79 ccw(c394.5,1839.89) C32.2@407.3,1827.09 ; C32.2@417.91,1816.48 cw(c430.71,1803.68) 430.71,1821.79 cw(c430.71,1839.89) C32.2@417.91,1827.09 ; C29.1@455.3,1163.48 ccw(c442.5,1150.68) 442.5,1168.79 ccw(c442.5,1186.89) C29.1@455.3,1174.09 ; C29.1@460.61,1168.79 324.12,1168.79 272.61,1220.31 U2.2@272.61,1287.63 ; C35.2@491.3,1816.48 ccw(c478.5,1803.68) 478.5,1821.79 ccw(c478.5,1839.89) 491.3,1827.09 ccw(c478.5,1839.89) 496.61,1839.89 ccw(c514.71,1839.89) C35.2@501.91,1827.09 ; C30.2@589.3,2039 ccw(c576.5,2026.2) 576.5,2044.31 ccw(c576.5,2062.41) C30.2@589.3,2049.61 ; v1(610,2186) 390,2186 198.61,1994.61 v1(198.61,1949.39) C34.1@198.61,1830.79 198.61,1760.31 272.61,1686.31 U2.1@272.61,1627.79 ; v1(783,1808) 845.61,1745.39 C28.1@845.61,1716.79 ; C28.1@840.3,1722.09 ccw(c827.5,1734.89) 845.61,1734.89 ccw(c863.71,1734.89) C28.1@850.91,1722.09 ; C20.1@844.61,1537.79 844.61,1447.79 844.61,1632.79 C28.1@844.61,1711.79 ; 844.61,1561.31 ccw(c866.13,1561.31) C20.1@850.91,1546.09 ; 844.61,1612.27 cw(c866.13,1612.27) C22.1@850.91,1627.48 ; 844.61,1653.31 ccw(c866.13,1653.31) C22.1@850.91,1638.09 ; 844.61,1696.27 cw(c866.13,1696.27) C28.1@850.91,1711.48 ; R28.1@855.3,2414 cw(c842.5,2401.2) 860.61,2401.2 cw(c878.71,2401.2) R28.1@865.91,2414 ; R28.1@860.61,2419.31 v2(860.61,2362.39) 860.61,2200.39 956,2105 v1(1062,2105) ; 1062,2238.69 ccw(c1034.69,2238.69) v1(1054,2258) ccw(c1034.69,2277.31) 1062,2277.31 ; 1062,2296.69 ccw(c1034.69,2296.69) v1(1054,2316) ccw(c1034.69,2335.31) 1062,2335.31 ; 1062,2367.51 ccw(c1041.51,2367.51) v1(1056,2382) ccw(c1041.51,2396.49) 1062,2396.49 ; v1(1309,1277) 1390,1277 v1(1444,1223) ; LED2.2@1326,2117 1326,1978 ; v1(1466,856) 1466,567 1466,140 1507,99 v1(1892,99) 1949.61,156.61 CN1.9@1949.61,226.79 ; 1468.5,603.5 1531.11,603.5 1549.61,622 B1.1@1549.61,673 ; B1.1@1542.76,666.15 cw(c1526.22,649.62) 1549.61,649.62 cw(c1572.99,649.62) B1.1@1556.45,666.15 ; U4.1@1616.15,2039.15 cw(c1599.62,2022.62) 1623,2022.62 cw(c1646.38,2022.62) U4.1@1629.85,2039.15 ; U4.1@1623,2046 1623,2015 1632,2006 C27.1@1632,1960 1344,1960 1326,1978 ; C27.1@1626.7,1954.7 ccw(c1613.89,1941.89) 1613.89,1960 ccw(c1613.89,1978.11) 1626.7,1965.3 ccw(c1613.89,1978.11) 1632,1978.11 ccw(c1650.11,1978.11) C27.1@1637.3,1965.3 ; 1782.95,2304 B2.1@1840.95,2246 ; 1817.69,2269.25 cw(c1794.44,2246) B2.1@1827.32,2246 ; CN2.8@1823.19,2706.79 ccw(c1759.41,2706.79) 1804.51,2751.89 ccw(c1849.61,2796.98) CN2.8@1849.61,2733.21 ; CN2.8@1849.61,2706.79 1752.39,2804 1458,2804 1062,2408 v1(1062,2105) ; CN1.9@1930.93,208.11 cw(c1885.83,163.01) 1949.61,163.01 cw(c2013.38,163.01) CN1.9@1968.29,208.11 ; v1(2222,1028) v1(2324,1130) ; C9.2@2379.3,909.48 cw(c2366.49,896.68) 2384.6,896.68 cw(c2402.71,896.68) 2389.9,909.48 cw(c2402.71,896.68) 2402.71,914.79 cw(c2402.71,932.89) C9.2@2389.9,920.09 ; C36.1@2384.6,766.79 C24.1@2470.93,766.79 2515,766.79 C10.1@2557.27,766.79 C7.1@2643.6,766.79 2643.6,704.4 v1(2649,699) cw(c2662.03,712.03) 2643.6,712.03 ; v1@2384.6,873.6 C9.2@2384.6,914.79 C4.2@2470.93,914.79 C3.1@2557.27,914.79 C1.1@2643.6,914.79 ; C36.1@2389.9,761.48 cw(c2402.71,748.68) 2402.71,766.79 cw(c2402.71,784.89) C36.1@2389.9,772.09 ; C24.1@2465.63,761.48 ccw(c2452.83,748.68) 2452.83,766.79 ccw(c2452.83,784.89) C24.1@2465.63,772.09 ; C4.2@2465.63,909.48 ccw(c2452.83,896.68) 2452.83,914.79 ccw(c2452.83,932.89) C4.2@2465.63,920.09 ; C24.1@2476.24,761.48 cw(c2489.04,748.68) 2489.04,766.79 cw(c2489.04,784.89) C24.1@2476.24,772.09 ; C4.2@2476.24,909.48 cw(c2489.04,896.68) 2489.04,914.79 cw(c2489.04,932.9) C4.2@2476.24,920.09 ; CN1.22@2530.93,345.47 ccw(c2485.83,390.57) 2549.61,390.57 ccw(c2613.38,390.57) CN1.22@2568.29,345.47 ; CN1.22@2549.61,326.79 2549.61,471.61 v1(2562,484) ; 2549.61,454.08 cw(c2591.92,454.08) v1(2562,484) ; 2549.61,466.47 cw(c2568.2,466.47) v1(2562,484) ; C10.1@2551.97,761.48 ccw(c2539.16,748.68) 2539.16,766.79 ccw(c2539.17,784.89) C10.1@2551.97,772.09 ; C3.1@2551.97,909.48 ccw(c2539.16,896.68) 2539.16,914.79 ccw(c2539.16,932.89) C3.1@2551.97,920.09 ; C10.1@2562.57,761.48 cw(c2575.38,748.68) 2575.38,766.79 cw(c2575.37,784.89) C10.1@2562.57,772.09 ; C3.1@2562.57,909.48 cw(c2575.38,896.68) 2575.38,914.79 cw(c2575.37,932.89) C3.1@2562.57,920.09 ; C7.1@2638.3,772.09 cw(c2625.5,784.89) 2625.5,766.79 cw(c2625.5,748.68) 2638.3,761.48 cw(c2625.5,748.68) 2643.6,748.68 cw(c2661.71,748.68) C7.1@2648.91,761.48 ; C1.1@2638.3,909.48 ccw(c2625.49,896.68) 2625.49,914.79 ccw(c2625.5,932.89) C1.1@2638.3,920.09 ; v1(3021,837) C11.2@3095.91,837 ; CN2.32@3049.61,2706.79 3107.87,2765.06 3291.34,2765.06 CN2.38@3349.61,2706.79 ; CN2.32@3049.61,2733.21 ccw(c3049.61,2796.98) 3094.7,2751.89 ccw(c3139.8,2706.79) CN2.32@3076.02,2706.79 ; 3075.41,837 cw(c3075.41,813.11) C11.2@3092.3,830 ; C11.2@3097.61,835.31 v1(3170.31,835.31) 3170.31,787 ; C12.2@3099.61,1071.31 v1(3168.31,1071.31) ; C11.2@3102.91,830 cw(c3115.71,817.2) 3115.71,835.31 cw(c3115.71,853.41) C11.2@3102.91,840.61 ; C12.2@3104.91,1066 cw(c3117.71,1053.2) 3117.71,1071.31 cw(c3117.71,1089.41) C12.2@3104.91,1076.61 ; R2.1@3133.7,662.3 ccw(c3120.89,675.11) 3139,675.11 ccw(c3157.11,675.11) R2.1@3144.3,662.3 ; R2.1@3139,657 3139,725 3170.31,756.31 3170.31,787 ; CN2.38@3323.19,2706.79 ccw(c3259.41,2706.79) 3304.51,2751.89 ccw(c3349.61,2796.98) CN2.38@3349.61,2733.21 ; C37.2@3351,739 3351,772 3336,787 3170.31,787 ; U2.2@272.61,1287.63 U2.4@108.04,1287.63 U2.3@108.04,1627.79 U2.1@272.61,1627.79 ; v1(1062,2105) 1062,2055 1139,1978 1326,1978 ; 844.61,1473.31 ccw(c866.13,1473.31) 850.91,1458.09 cw(c866.13,1473.31) 844.61,1473.31 ; 844.61,1520.27 cw(c866.13,1520.27) 850.91,1535.48 ccw(c866.13,1520.27) 844.61,1520.27
  Bottom Layer w10: v1@1402.46,1965.53 ccw(c1393.93,1974.07) 1406,1974.07 ccw(c1418.07,1974.07) v1@1409.54,1965.53 ; v1@1402.46,2056.46 cw(c1393.93,2047.93) 1406,2047.93 cw(c1418.07,2047.93) v1@1409.54,2056.46 ; v1(1406,1962) v1(1406,2060) ; v1@2250.46,941.46 cw(c2241.93,932.93) 2254,932.93 cw(c2266.07,932.93) v1@2257.54,941.46 ; v1(2254,945) 2254,672 2258,668 v1(2258,453) ; v1@2254.46,456.54 ccw(c2245.93,465.07) 2258,465.07 ccw(c2270.07,465.07) v1@2261.54,456.54 ; 2366,2429.66 2400.19,2463.85 2400.19,2656.2 2449.61,2705.62 CN2.20@2449.61,2706.79 ; 2416.1,2672.12 ccw(c2386.44,2701.78) CN2.20@2428.26,2705.09 ; 2416.93,2672.94 cw(c2447.05,2642.82) CN2.20@2448.75,2685.39 ; CN2.20@2418.29,2704.3 cw(c2358.04,2699.52) 2400.78,2656.79 cw(c2445.82,2611.75) CN2.20@2448.35,2675.4 ; v1@2420.46,2023.54 ccw(c2411.93,2032.07) 2424,2032.07 ccw(c2436.07,2032.07) v1@2427.54,2023.54 ; v1(2424,2020) 2424,2137 ; v1@2451,1049 cw(c2451,1036.93) 2459.54,1045.46 cw(c2468.07,1054) v1@2456,1054 ; v1(2451,1054) 2465,1040 v1(2465,872) v1(2465,713.82) 2562,616.82 v1(2562,484) ; v1@2461.46,717.36 ccw(c2452.93,725.89) 2465,725.89 ccw(c2477.07,725.89) v1@2468.54,717.36 ; v1@2461.46,868.46 cw(c2452.93,859.93) 2465,859.93 cw(c2477.07,859.93) v1@2468.54,868.46 ; v1@2461.46,875.54 ccw(c2452.93,884.07) 2465,884.07 ccw(c2477.07,884.07) v1@2468.54,875.54 ; v1@2465,708.82 cw(c2465,696.75) 2473.54,705.29 cw(c2482.07,713.82) v1@2470,713.82 ; 2474.04,704.78 ccw(c2488,718.74) v1@2488,699 ; v1@2493,694 ccw(c2512.74,694) 2498.78,680.04 ; 2511.16,667.67 cw(c2470.49,627) v1@2528,627 ; 2528.23,650.6 cw(c2504.63,627) v1@2538,627 ; v1@2532.73,631.99 cw(c2534.36,602.04) 2555.57,623.25 ; v1@2558.46,487.54 ccw(c2549.93,496.07) 2562,496.07 ccw(c2574.07,496.07) v1@2565.54,487.54
  Bottom Layer w20: U2.4@98.41,1278 cw(c75.15,1254.75) 108.04,1254.75 cw(c140.93,1254.75) U2.4@117.67,1278 ; U2.4@108.04,1287.63 v1(108.04,913) 108.04,870.96 221.61,757.39 221.61,313.39 P1.2@414,121 ; DAPEN.2@160,563 218.61,563 ; DAPEN.2@179.79,545.51 cw(c218.6,511.21) 218.6,563 cw(c218.6,614.79) DAPEN.2@179.79,580.49 ; v1(198.61,1949.39) v1(342.39,1949.39) ; U2.2@272.61,1287.63 272.61,1300.22 U2.2@285.04,1300.22 ; U2.1@272.61,1627.79 531.21,1627.79 557.61,1601.39 v2(557.61,1503.79) v1(557.61,1455.79) ; U2.1@297.99,1618.16 cw(c321.24,1594.9) 321.24,1627.79 cw(c321.24,1660.67) U2.1@297.99,1637.42 ; P1.2@394.47,121 ccw(c347.33,121) 380.66,154.34 ccw(c414,187.67) P1.2@414,140.53 ; v1(496.61,1896) 540.61,1852 739,1852 v1(783,1808) 853.4,1808 945.58,1715.82 1013.82,1715.82 1057,1759 v1(1162,1759) 1162,1597 1121,1556 SWD.2@1073,1556 1172.21,1456.79 1172.21,1413.79 v1(1309,1277) 1171,1139 v1(1111,1139) ; 585,2480.51 ccw(c564.51,2480.51) v1(579,2495) 585,2489 v1(585,2350) 585,2211 v1(610,2186) 747,2186 860.61,2299.61 v2(860.61,2362.39) ; SWD.2@1073,1536.47 cw(c1073,1489.33) 1106.34,1522.66 cw(c1139.67,1556) SWD.2@1092.53,1556 ; SWD.2@1086.81,1542.19 cw(c1120.14,1508.86) 1120.14,1556 cw(c1120.14,1603.14) SWD.2@1086.81,1569.81 ; v1(1444,1223) 1467,1200 1467,857 v1(1466,856) ; CN2.8@1849.61,2680.37 cw(c1849.61,2616.59) 1894.7,2661.69 cw(c1939.8,2706.79) 1876.02,2706.79 cw(c1939.8,2706.79) 1894.7,2751.89 cw(c1849.61,2796.98) CN2.8@1849.61,2733.21 ; v1(1892,99) 2321.82,99 CN1.19@2449.61,226.79 CN1.20@2449.61,326.79 CN1.22@2549.61,326.79 ; CN2.9@1923.19,2606.79 ccw(c1859.41,2606.79) 1904.51,2651.89 ccw(c1949.61,2696.98) CN2.9@1949.61,2633.21 ; CN2.9@1949.61,2606.79 CN2.8@1849.61,2706.79 1920.82,2778 2378.39,2778 CN2.20@2449.61,2706.79 2520.45,2777.63 2978.76,2777.63 CN2.32@3049.61,2706.79 ; 2366,2429.66 2366,2195 2417,2144 2986,2144 v1(3151,2309) ; CN1.19@2423.19,226.79 cw(c2359.41,226.79) 2404.51,181.69 cw(c2449.61,136.59) CN1.19@2449.61,200.37 ; CN2.20@2423.19,2706.79 ccw(c2359.41,2706.79) 2404.51,2751.89 ccw(c2449.61,2796.98) 2449.61,2733.21 ccw(c2449.61,2796.98) 2494.7,2751.88 ccw(c2539.8,2706.79) CN2.20@2476.02,2706.79 ; CN1.19@2430.93,245.47 ccw(c2385.83,290.57) 2449.61,290.57 ccw(c2513.38,290.57) CN1.19@2468.29,245.47 ; CN1.20@2430.93,308.11 cw(c2385.83,263.01) 2449.61,263.01 cw(c2513.38,263.01) 2468.29,308.11 cw(c2513.38,263.01) 2513.38,326.79 cw(c2513.38,390.57) CN1.20@2468.29,345.47 ; CN1.22@2530.93,308.11 ccw(c2485.83,263.01) 2485.83,326.79 ccw(c2485.83,390.57) CN1.22@2530.93,345.47 ; 2850.13,715.99 ccw(c2867,732.86) v1(2867,709) ; v1(2852,471) 2872,491 2872,694.12 2823,743.12 2823,904.88 2868.12,950 2908,950 v1(3021,837) ; CN2.32@3023.19,2706.79 ccw(c2959.41,2706.79) 3004.51,2751.88 ccw(c3049.61,2796.98) CN2.32@3049.61,2733.21 ; v1(3168.31,1071.31) 3170.31,1069.31 3170.31,936.66 3170,936.36 3170,835.61 v1(3170.31,835.31) ; v1(3192,2310) 3317,2310 3442,2435 3442,2614.39 CN2.38@3349.61,2706.79 ; CN2.38@3349.61,2680.37 cw(c3349.61,2616.59) 3394.7,2661.69 cw(c3439.8,2706.79) CN2.38@3376.02,2706.79 ; v1(2867,709) cw(c2854.93,696.93) 2872,696.93 ccw(c2854.93,696.93) v1(2867,709)
  other v1: 1061,-32 914,-25 3471,-10 1122,-8 3631,23 914,34 1062,36 867,38 1120,64 3721,94 915,100 1061,102 3426,102 870,103 1356,140 883,190 3579,192 3741,221 682,222 3458,240 910,245 1356,251.8 1064,258 911,294 876,327 3575,360 1356,363.6 913,370 3737,371 3459,372 1064,395.33 3123,402 3883,402 2950,414 1728,425 913,433 3274,444 3573,450 2043,466 2950,469 3459,471 1356,475.4 3211,511 3940,529 1064,532.67 1923,538 1829,540 1866,573 3246,581 1356,587.2 2533,627 2240,666 2162,668 1064,670 2488,694 1356,699 3888,704 3483,705 458,708 2610,708 3986,727 497,751 3567,760 2864,800 3887,814 3999,820 4083,821 2384,873 3953,901 4211,926 4129,967 3401,974 3878,979 4051,989 3916,1021 3328,1048 2150,1055 2348,1084 2123,1087 4212,1090 3981,1111 3236,1133 3876,1134 1041,1139 4130,1149 3556,1163 2670,1171 863,1181 1041,1183 1111,1183 3927,1197 2669,1203 2123,1206 4069,1212 862,1214 3035,1214 2882,1219 1868,1224 2640,1230 4214,1234 3479,1238 2712,1247 2123,1256 1530,1280 2123,1285 2671,1291 4130,1295 4000,1302 483,1308 1870,1310 2772,1310 3882,1324 3493,1330 1658,1338 2738,1345 3206,1354 1871,1370 1935,1372 3180,1377 3534,1382 3935,1384 1530,1391 1659,1404 4068,1407 4216,1409 1935,1416 1871,1419 3857,1426 3493,1428 3251,1429 3174,1430 4006,1451 1660,1467 3894,1469 4131,1470 2467,1479 3391,1489 3218,1499 3139,1503 1194,1523 1661,1537 2316,1557 3242,1559 2724,1561 2790,1561 2855,1561 2919,1561 1300,1573 4070,1577 1806,1589 3311,1589 1258,1597 4213,1600 1301,1608 4011,1626 1556,1638 2227,1657 1578,1660 1302,1674 4130,1678 2268,1695 1791,1721 1301,1723 2116,1730 2213,1730 1882,1750 1791,1758 3531,1771 1882,1786 2115,1786 2986,1787 3043,1787 4214,1792 4011,1814 2113,1836 3543,1866 4130,1875 3397,1899 2981,1921 2904,1922 3061,1922 3369,1931 4066,1958 4011,1983 3011,1988 2868,1989 2940,1989 4220,2002 912,2003 1040,2033 4135,2046 914,2087 2924,2096 4010,2135 2656,2144 3652,2159 3492,2160 1897,2161 4070,2164 2923,2168 4216,2168 3769,2179 2532,2180 2487,2181 2627,2182 918,2212 2923,2230 4132,2236 1995,2239 3552,2260 4009,2278 3653,2283 918,2284 1833,2314 3726,2326 469,2352 3489,2370 4212,2371 4119,2388 3649,2417 3550,2465 4146,2499 3977,2523 3486,2555 4018,2621 3864,2638 3907,2732 3756,2743 2150,2778 2344,2778 2641,2778 2473,2789 3575,2810 3650,2814 3718,2817 2179,2821 3634,2872 3195.95,2888 2297.52,2889 3295.78,2890 2597,2891 2796.65,2891 2896.47,2891 3423,2891 2397.34,2892 2497.17,2892 2696.82,2892 2996.3,2892 3096.13,2892 3474,2892
  other v2: 557.61,1410.79 595.61,1410.79 634.61,1410.79 595.61,1455.79 634.61,1455.79 595.61,1503.79 634.61,1503.79
LINK_LEDG: R33.1 U3.5 | length 985.6
  Top Layer w10: U3.5@586.76,1558.18 586.76,1606.46 669.61,1689.31 669.61,2405.31 655.61,2419.31 R33.1@618.61,2419.31 ; R33.1@627.45,2410.47 cw(c648.78,2389.13) 648.78,2419.31 cw(c648.78,2449.49) R33.1@627.45,2428.15
LINK_LEDR: R32.1 U3.6 | length 811.9
  Top Layer w10: U3.6@567.08,1558.18 567.08,1619.78 644.61,1697.31 644.61,2253.79 R32.1@618.61,2279.79 ; R32.1@618.61,2267.29 cw(c618.61,2237.11) 639.95,2258.45 cw(c661.28,2279.79) R32.1@631.11,2279.79
LINK_RESET: P1.5 R50.2 R54.1 SWD.5 | length 2687.6
  Top Layer w10: R50.2@695,900 728.98,900 791,837.98 v1(791,760) 1020,760 1073,813 SWD.5@1073,1256 1278,1461 R54.1@1405,1461 ; R50.2@703.84,891.16 cw(c725.18,869.82) 725.18,900 cw(c725.18,930.18) R50.2@703.84,908.84 ; v1@787.46,763.54 ccw(c778.93,772.07) 791,772.07 ccw(c803.07,772.07) 794.54,763.54 ccw(c803.07,772.07) 803.07,760 ccw(c803.07,747.93) v1@794.54,756.46 ; SWD.5@1055.66,1238.66 cw(c1013.79,1196.79) 1073,1196.79 cw(c1132.21,1196.79) SWD.5@1090.34,1238.66 ; SWD.5@1062.73,1245.73 cw(c1037.93,1220.93) 1073,1220.93 cw(c1108.07,1220.93) SWD.5@1083.27,1245.73 ; SWD.5@1073,1270.53 ccw(c1073,1305.6) 1097.8,1280.8 ccw(c1122.6,1256) SWD.5@1087.53,1256 ; SWD.5@1073,1280.53 ccw(c1073,1339.74) 1114.87,1297.87 ccw(c1156.74,1256) SWD.5@1097.53,1256 ; R54.1@1396.16,1452.16 ccw(c1374.82,1430.82) 1374.82,1461 ccw(c1374.82,1491.18) R54.1@1396.16,1469.84
  Bottom Layer w10: P1.5@689.47,121 ccw(c630.26,121) 672.13,162.87 ccw(c714,204.74) P1.5@714,145.53 ; P1.5@699.47,121 ccw(c664.4,121) 689.2,145.8 ccw(c714,170.6) P1.5@714,135.53 ; P1.5@714,121 645,190 645,614 v1(791,760) ; v1@786,760 cw(c773.93,760) 782.46,751.46 cw(c791,742.93) v1@791,755
LINK_SWCLK: P1.4 R8.1 R51.2 | length 1643.6
  Top Layer w10: R51.2@694,985 R8.1@811,985 v1(871,985) ; R51.2@702.84,976.16 cw(c724.18,954.82) 724.18,985 cw(c724.18,1015.18) R51.2@702.84,993.84 ; R8.1@802.16,976.16 ccw(c780.82,954.82) 780.82,985 ccw(c780.82,1015.18) R8.1@802.16,993.84 ; R8.1@819.84,976.16 cw(c841.18,954.82) 841.18,985 cw(c841.18,1015.18) R8.1@819.84,993.84 ; v1@867.46,981.47 ccw(c858.93,972.93) 858.93,985 ccw(c858.93,997.07) v1@867.46,988.54
  Bottom Layer w10: P1.4@614,96.47 cw(c614,37.26) 655.87,79.13 cw(c697.74,121) P1.4@638.53,121 ; P1.4@614,106.47 cw(c614,71.4) 638.8,96.2 cw(c663.6,121) P1.4@628.53,121 ; P1.4@614,121 676,59 751,59 788,96 788,706 871,789 v1(871,985) ; v1@867.46,981.47 cw(c858.93,972.93) 871,972.93 cw(c883.07,972.93) v1@874.54,981.47
LINK_SWDIO: P1.3 R7.1 R42.2 R43.2 | length 2077.4
  Top Layer w10: R43.2@685.16,1078.84 ccw(c661.41,1102.59) 695,1102.59 ; R42.2@686.16,1146.16 cw(c664.82,1124.82) 695,1124.82 cw(c725.18,1124.82) R42.2@703.84,1146.16 ; 695,1097.76 ccw(c721.76,1097.76) 702.84,1078.84 ccw(c724.18,1100.18) 724.18,1070 ccw(c724.18,1039.82) R43.2@702.84,1061.16 ; R42.2@695,1155 695,1071 R43.2@694,1070 809,1070 R7.1@810,1071 v1(867,1071) ; 777.41,1070 ccw(c777.41,1103.59) R7.1@801.16,1079.84 ; 782.24,1070 cw(c782.24,1043.24) R7.1@801.16,1062.16 ; R7.1@818.84,1062.16 cw(c840.18,1040.82) 840.18,1071 cw(c840.18,1101.18) R7.1@818.84,1079.84 ; v1@863.47,1067.46 ccw(c854.93,1058.93) 854.93,1071 ccw(c854.93,1083.07) v1@863.47,1074.53
  Bottom Layer w10: P1.3@514,96.47 cw(c514,37.26) 555.87,79.13 cw(c597.74,121) P1.3@538.53,121 ; P1.3@514,106.47 cw(c514,71.4) 538.8,96.2 cw(c563.6,121) P1.3@528.53,121 ; P1.3@514,121 606,29 759,29 809.46,79.46 809.46,694.46 898,783 898,1040 887,1051 v1(867,1071) ; v1@867,1066 cw(c867,1053.93) 875.54,1062.46 cw(c884.07,1071) v1@872,1071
